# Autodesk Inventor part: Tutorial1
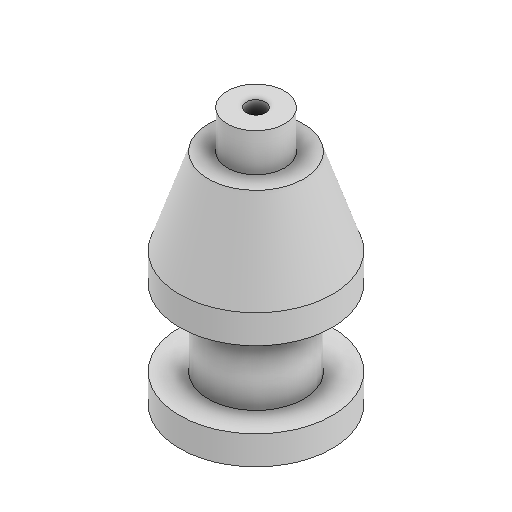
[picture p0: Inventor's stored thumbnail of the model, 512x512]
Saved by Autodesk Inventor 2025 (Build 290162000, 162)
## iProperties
Created: 2022-07
Part Number: Tutorial1
Material: Generic
Document SubType Name: Modeling
Designer: LENOVO-CADCIM
Density: 1 g/cm^3
Appearance: Default
Author: LENOVO-CADCIM
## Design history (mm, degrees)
sketch "Sketch1"
  geometry: L1 (10, 0)-(10, 270); L2 (10, 270)-(30, 270); L3 (30, 270)-(30, 230); L4 (30, 230)-(50, 230); L5 (50, 230)-(80, 140); L6 (80, 140)-(80, 110); L7 (80, 110)-(50, 110); L8 (50, 110)-(50, 30); L9 (50, 30)-(80, 30); L10 (80, 30)-(80, 0); L11 (80, 0)-(10, 0); L12 (0, 0)-(0, 270)
  constraints: 24 end point, 8 perpendicular, 2 vertical, 1 collinear, 1 parallel, 1 point on line
  dimensions: "d0" = 30 distance between parallel lines of L11 L9; "d1" = 80 distance between parallel lines of L7 L9; "d2" = 30 distance of L5.end L6.end; "d3" = 230 distance between parallel lines of L4 L11; "d4" = 40 distance between parallel lines of L4 L2; "d6" = 160 diameter of L10.end L12; "d7" = 100 diameter of L8 L12; "d8" = 20 diameter of L1 L12; "d9" = 60 diameter of L3 L12; "d10" = 100 diameter of L4.end L12
revolve "Revolution1" sketch "Sketch1" stored, may be unused: angle "d11" = 90 deg
body "Solid1"
